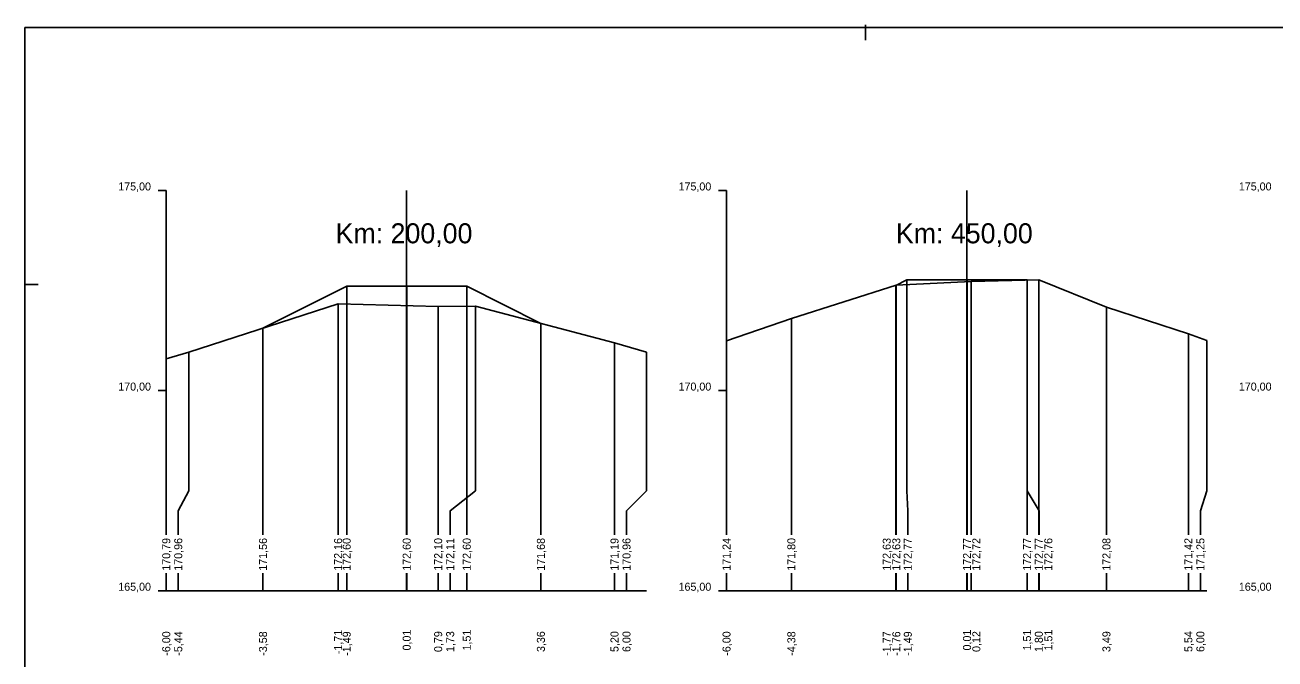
# Model space of a CAD drawing. Extents: x -614174 to -599765, y -1185887 to -1181080.
# Drawn here: x -601084.96 to -601053.72, y -1184399.05 to -1184383.21 of the extents above; entities that cross this region are included whole.
import ezdxf

# ---------------------------------------------------------------- set-up
doc = ezdxf.new("R2010")
doc.units = 0
for name, color, linetype in [('11', 7, 'Continuous'), ('16', 7, 'Continuous'), ('21', 7, 'Continuous'), ('28', 7, 'Continuous'), ('59', 7, 'Continuous'), ('8', 7, 'Continuous'), ('návrh', 7, 'Continuous')]:
    doc.layers.add(name, color=color, linetype=linetype)

msp = doc.modelspace()

# ---------------------------------------------------------------- linework, layer by layer
for points in [[(-601067.427, -1184391.098), (-601065.808, -1184390.545), (-601063.186, -1184389.712), (-601061.311, -1184389.618), (-601059.625, -1184389.571), (-601057.935, -1184390.26), (-601055.888, -1184390.92), (-601055.427, -1184391.092)], [(-601063.199, -1184389.716), (-601062.919, -1184389.577), (-601061.419, -1184389.577), (-601059.919, -1184389.577), (-601059.915, -1184389.579)], [(-601062.919, -1184389.577), (-601062.919, -1184389.577), (-601062.919, -1184389.577)], [(-601061.419, -1184389.577), (-601061.419, -1184389.577), (-601061.419, -1184389.577)], [(-601059.919, -1184389.577), (-601059.919, -1184389.577), (-601059.919, -1184389.577)], [(-601079.01, -1184390.783), (-601076.919, -1184389.737), (-601075.419, -1184389.737), (-601073.919, -1184389.737), (-601072.066, -1184390.664)], [(-601076.919, -1184389.737), (-601076.919, -1184389.737), (-601076.919, -1184389.737)], [(-601075.419, -1184389.737), (-601075.419, -1184389.737), (-601075.419, -1184389.737)], [(-601073.919, -1184389.737), (-601073.919, -1184389.737), (-601073.919, -1184389.737)], [(-601063.199, -1184389.716), (-601063.199, -1184389.716), (-601063.199, -1184389.716)], [(-601081.427, -1184391.548), (-601080.863, -1184391.381), (-601077.134, -1184390.178), (-601074.633, -1184390.239), (-601073.699, -1184390.232), (-601070.227, -1184391.151), (-601069.427, -1184391.386)], [(-601079.01, -1184390.783), (-601079.01, -1184390.783), (-601079.011, -1184390.783)]]:
    msp.add_lwpolyline(points)
at = {"layer": '11'}
for points in [[(-601062.919, -1184389.577), (-601062.919, -1184394.842), (-601062.899, -1184395.342), (-601062.899, -1184395.944)], [(-601061.419, -1184389.577), (-601061.419, -1184394.842), (-601061.419, -1184395.342), (-601061.419, -1184395.944)], [(-601061.311, -1184389.618), (-601061.311, -1184394.842), (-601061.311, -1184395.342), (-601061.311, -1184395.944)], [(-601059.919, -1184389.577), (-601059.919, -1184394.842), (-601059.919, -1184395.342), (-601059.919, -1184395.944)], [(-601059.915, -1184389.579), (-601059.915, -1184394.842), (-601059.619, -1184395.342), (-601059.619, -1184395.944)], [(-601059.625, -1184389.571), (-601059.625, -1184394.842), (-601059.625, -1184395.342), (-601059.625, -1184395.944)], [(-601076.919, -1184389.737), (-601076.919, -1184394.842), (-601076.919, -1184395.342), (-601076.919, -1184395.944)], [(-601075.419, -1184389.737), (-601075.419, -1184394.842), (-601075.419, -1184395.342), (-601075.419, -1184395.944)], [(-601073.919, -1184389.737), (-601073.919, -1184394.842), (-601073.919, -1184395.342), (-601073.919, -1184395.944)], [(-601063.199, -1184389.716), (-601063.199, -1184394.842), (-601063.199, -1184395.342), (-601063.199, -1184395.944)], [(-601063.186, -1184389.712), (-601063.186, -1184394.842), (-601063.186, -1184395.342), (-601063.186, -1184395.944)], [(-601077.134, -1184390.178), (-601077.134, -1184394.842), (-601077.134, -1184395.342), (-601077.134, -1184395.944)], [(-601074.633, -1184390.239), (-601074.633, -1184394.842), (-601074.633, -1184395.342), (-601074.633, -1184395.944)], [(-601073.699, -1184390.232), (-601073.699, -1184394.842), (-601074.333, -1184395.342), (-601074.333, -1184395.944)], [(-601057.935, -1184390.26), (-601057.935, -1184394.842), (-601057.935, -1184395.342), (-601057.935, -1184395.944)], [(-601065.808, -1184390.545), (-601065.808, -1184394.842), (-601065.808, -1184395.342), (-601065.808, -1184395.944)], [(-601079.01, -1184390.783), (-601079.01, -1184394.842), (-601079.01, -1184395.342), (-601079.01, -1184395.944)], [(-601072.066, -1184390.664), (-601072.066, -1184394.842), (-601072.066, -1184395.342), (-601072.066, -1184395.944)], [(-601055.888, -1184390.92), (-601055.888, -1184394.842), (-601055.888, -1184395.342), (-601055.888, -1184395.944)], [(-601070.227, -1184391.151), (-601070.227, -1184394.842), (-601070.227, -1184395.342), (-601070.227, -1184395.944)], [(-601067.427, -1184391.098), (-601067.427, -1184394.842), (-601067.427, -1184395.342), (-601067.427, -1184395.944)], [(-601055.427, -1184391.092), (-601055.427, -1184394.842), (-601055.588, -1184395.342), (-601055.588, -1184395.944)], [(-601081.427, -1184391.548), (-601081.427, -1184394.842), (-601081.427, -1184395.342), (-601081.427, -1184395.944)], [(-601080.863, -1184391.381), (-601080.863, -1184394.842), (-601081.127, -1184395.342), (-601081.127, -1184395.944)], [(-601069.427, -1184391.386), (-601069.427, -1184394.842), (-601069.927, -1184395.342), (-601069.927, -1184395.944)], [(-601081.427, -1184396.902), (-601081.427, -1184397.342)], [(-601081.127, -1184396.902), (-601081.127, -1184397.342)], [(-601079.01, -1184396.902), (-601079.01, -1184397.342)], [(-601077.134, -1184396.902), (-601077.134, -1184397.342)], [(-601076.919, -1184396.902), (-601076.919, -1184397.342)], [(-601075.419, -1184396.902), (-601075.419, -1184397.342)], [(-601074.633, -1184396.902), (-601074.633, -1184397.342)], [(-601074.333, -1184396.902), (-601074.333, -1184397.342)], [(-601073.919, -1184396.902), (-601073.919, -1184397.342)], [(-601072.066, -1184396.902), (-601072.066, -1184397.342)], [(-601070.227, -1184396.902), (-601070.227, -1184397.342)], [(-601069.927, -1184396.902), (-601069.927, -1184397.342)], [(-601067.427, -1184396.902), (-601067.427, -1184397.342)], [(-601065.808, -1184396.902), (-601065.808, -1184397.342)], [(-601063.199, -1184396.902), (-601063.199, -1184397.342)], [(-601063.186, -1184396.902), (-601063.186, -1184397.342)], [(-601062.899, -1184396.902), (-601062.899, -1184397.342)], [(-601061.419, -1184396.902), (-601061.419, -1184397.342)], [(-601061.311, -1184396.902), (-601061.311, -1184397.342)], [(-601059.919, -1184396.902), (-601059.919, -1184397.342)], [(-601059.625, -1184396.902), (-601059.625, -1184397.342)], [(-601059.619, -1184396.902), (-601059.619, -1184397.342)], [(-601057.935, -1184396.902), (-601057.935, -1184397.342)], [(-601055.888, -1184396.902), (-601055.888, -1184397.342)], [(-601055.588, -1184396.902), (-601055.588, -1184397.342)]]:
    msp.add_lwpolyline(points, dxfattribs=at)
at = {"layer": '16'}
for p, q in [((-601081.427, -1184397.342), (-601069.427, -1184397.342)), ((-601067.427, -1184397.342), (-601055.427, -1184397.342))]:
    msp.add_line(p, q, dxfattribs=at)
for points in [[(-601059.915, -1184389.579), (-601059.915, -1184389.579)], [(-601059.915, -1184389.579), (-601059.915, -1184389.579)], [(-601072.066, -1184390.664), (-601072.066, -1184390.664), (-601072.065, -1184390.664)]]:
    msp.add_lwpolyline(points, dxfattribs=at)
at = {"layer": '21'}
for p, q in [((-601081.627, -1184387.342), (-601081.427, -1184387.342)), ((-601067.627, -1184387.342), (-601067.427, -1184387.342)), ((-601081.627, -1184392.342), (-601081.427, -1184392.342)), ((-601067.627, -1184392.342), (-601067.427, -1184392.342)), ((-601081.627, -1184397.342), (-601081.427, -1184397.342)), ((-601067.627, -1184397.342), (-601067.427, -1184397.342))]:
    msp.add_line(p, q, dxfattribs=at)
at = {"layer": '28'}
for p, q in [((-601075.427, -1184395.944), (-601075.427, -1184387.342)), ((-601061.427, -1184395.944), (-601061.427, -1184387.342)), ((-601075.427, -1184397.342), (-601075.427, -1184396.902)), ((-601061.427, -1184397.342), (-601061.427, -1184396.902))]:
    msp.add_line(p, q, dxfattribs=at)
at = {"layer": '8'}
for p, q in [((-601081.427, -1184395.944), (-601081.427, -1184387.342)), ((-601067.427, -1184395.944), (-601067.427, -1184387.342)), ((-601081.427, -1184397.342), (-601081.427, -1184396.902)), ((-601067.427, -1184397.342), (-601067.427, -1184396.902))]:
    msp.add_line(p, q, dxfattribs=at)
at = {"layer": 'návrh'}
for p, q in [((-601084.957, -1184389.69), (-601084.957, -1184383.271)), ((-601084.957, -1184383.271), (-600937.957, -1184383.271)), ((-601063.957, -1184383.59), (-601063.957, -1184383.209)), ((-601084.957, -1184419.39), (-601084.957, -1184389.69)), ((-601084.957, -1184389.69), (-601084.631, -1184389.69))]:
    msp.add_line(p, q, dxfattribs=at)

# ---------------------------------------------------------------- texts
at = {"layer": '16'}
for s, p in [('170,79', (-601081.327, -1184396.842)), ('170,96', (-601081.027, -1184396.842)), ('171,56', (-601078.91, -1184396.842)), ('172,16', (-601077.034, -1184396.842)), ('172,60', (-601076.819, -1184396.842)), ('172,60', (-601075.319, -1184396.842)), ('172,10', (-601074.533, -1184396.842)), ('172,11', (-601074.233, -1184396.842)), ('172,60', (-601073.819, -1184396.842)), ('171,68', (-601071.966, -1184396.842)), ('171,19', (-601070.127, -1184396.842)), ('170,96', (-601069.827, -1184396.842)), ('171,24', (-601067.327, -1184396.842)), ('171,80', (-601065.708, -1184396.842)), ('172,63', (-601063.325, -1184396.842)), ('172,63', (-601063.086, -1184396.842)), ('172,77', (-601062.799, -1184396.842)), ('172,77', (-601061.319, -1184396.842)), ('172,72', (-601061.086, -1184396.842)), ('172,77', (-601059.819, -1184396.842)), ('172,77', (-601059.525, -1184396.842)), ('172,76', (-601059.287, -1184396.842)), ('172,08', (-601057.835, -1184396.842)), ('171,42', (-601055.788, -1184396.842)), ('171,25', (-601055.488, -1184396.842))]:
    msp.add_text(s, height=0.2, rotation=90, dxfattribs=at).set_placement(p)
at = {"layer": '21'}
for s, p in [('175,00', (-601082.627, -1184387.342)), ('175,00', (-601068.627, -1184387.342)), ('175,00', (-601054.627, -1184387.342)), ('170,00', (-601082.627, -1184392.342)), ('170,00', (-601068.627, -1184392.342)), ('170,00', (-601054.627, -1184392.342)), ('165,00', (-601082.627, -1184397.342)), ('165,00', (-601068.627, -1184397.342)), ('165,00', (-601054.627, -1184397.342))]:
    msp.add_text(s, height=0.2, dxfattribs=at).set_placement(p)
at = {"layer": '28'}
for s, p in [('Km: 200,00', (-601077.196, -1184388.663)), ('Km: 450,00', (-601063.196, -1184388.663))]:
    msp.add_text(s, height=0.5, dxfattribs=at).set_placement(p)
at = {"layer": '59'}
for s, p in [('-6,00', (-601081.327, -1184398.965)), ('-5,44', (-601081.027, -1184398.965)), ('-3,58', (-601078.91, -1184398.966)), ('-1,71', (-601077.034, -1184398.927)), ('-1,49', (-601076.819, -1184398.966)), ('0,01', (-601075.319, -1184398.834)), ('0,79', (-601074.533, -1184398.873)), ('1,73', (-601074.233, -1184398.873)), ('1,51', (-601073.819, -1184398.834)), ('3,36', (-601071.966, -1184398.873)), ('5,20', (-601070.127, -1184398.872)), ('6,00', (-601069.827, -1184398.872)), ('-6,00', (-601067.327, -1184398.965)), ('-4,38', (-601065.708, -1184398.966)), ('-1,77', (-601063.325, -1184398.966)), ('-1,76', (-601063.086, -1184398.966)), ('-1,49', (-601062.799, -1184398.966)), ('0,01', (-601061.319, -1184398.834)), ('0,12', (-601061.086, -1184398.871)), ('1,51', (-601059.819, -1184398.834)), ('1,80', (-601059.525, -1184398.872)), ('1,51', (-601059.287, -1184398.834)), ('3,49', (-601057.835, -1184398.873)), ('5,54', (-601055.788, -1184398.872)), ('6,00', (-601055.488, -1184398.872))]:
    msp.add_text(s, height=0.2, rotation=90, dxfattribs=at).set_placement(p)

doc.saveas('drawing.dxf')
